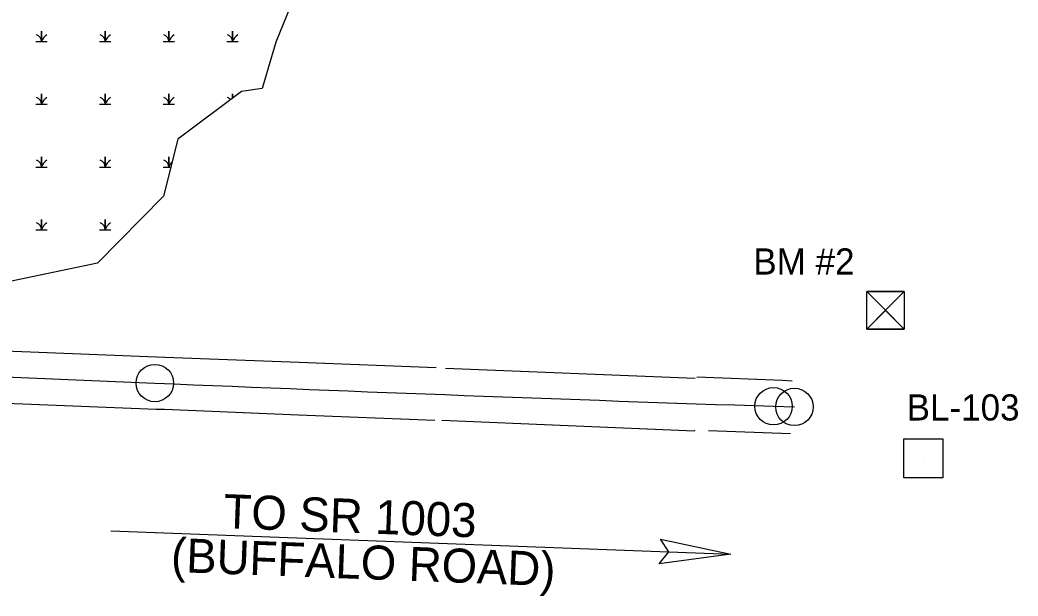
# Model space of a CAD drawing. Extents: x 2169223 to 2172151, y 723262 to 725175.
# Drawn here: x 2171308.7 to 2171689.8, y 723974.6 to 724194.7 of the extents above; entities that cross this region are included whole.
import ezdxf

# ---------------------------------------------------------------- set-up
doc = ezdxf.new("R2010")
doc.units = 0
for name, color, linetype in [('CTL Bench Mark CELL', 7, 'Continuous'), ('CTL Bench Mark Text', 7, 'Continuous'), ('CTL Supplemental Horizontal and Vertical CELL', 7, 'Continuous'), ('CTL Supplemental Horizontal and Vertical Text', 7, 'Continuous'), ('Default', 7, 'Continuous'), ('Exist Roads EOP', 7, 'Continuous'), ('Prop Horizontal Alignment', 7, 'Continuous'), ('Prop Horizontal Alignment Station Label', 7, 'Continuous')]:
    doc.layers.add(name, color=color, linetype=linetype)

# ---------------------------------------------------------------- blocks, each defined once
blk = doc.blocks.new('CTL BENCH MARK')
at = {"layer": 'CTL Bench Mark CELL'}
blk.add_line((0, 0), (0, 0), dxfattribs=at)
blk.add_lwpolyline([(-0.072, 0.07175), (0.07175, 0.07175), (0.07175, -0.072), (-0.072, -0.072)], close=True, dxfattribs=at)
for points in [[(0.07175, 0.07175), (-0.072, -0.072), (-0.000125, -0.000125), (0.07175, -0.072), (-0.072, 0.07175)], [(-0.000125, -0.000125), (0.07175, 0.07175), (-0.072, 0.07175), (-0.000125, -0.000125)], [(-0.000125, -0.000125), (-0.072, -0.072), (0.07175, -0.072), (-0.000125, -0.000125)]]:
    blk.add_lwpolyline(points, dxfattribs=at)
blk = doc.blocks.new('CTL SUPPLEMENTAL HORIZONTAL AND VERTICAL')
at = {"layer": 'CTL Supplemental Horizontal and Vertical CELL'}
blk.add_line((0, 0), (0, 0), dxfattribs=at)
blk.add_lwpolyline([(-0.0735, 0.074), (0.07475, 0.074), (0.07475, -0.0745), (-0.0735, -0.0745)], close=True, dxfattribs=at)

msp = doc.modelspace()

# ---------------------------------------------------------------- linework, layer by layer
at = {"layer": 'Default'}
msp.add_line((2171343.36, 723999.51), (2171580.07, 723990.65), dxfattribs=at)
for points in [[(2171646.71, 724409.08), (2171639.12, 724404.07), (2171615.95, 724359.66), (2171585.14, 724346.96), (2171572.27, 724330.12), (2171541.38, 724278.6), (2171494.05, 724272.59), (2171450.52, 724247.37), (2171445.92, 724243.67), (2171427.74, 724238.82), (2171406.38, 724186.3), (2171401.13, 724168.54), (2171393.3, 724167.45), (2171368.95, 724149.15), (2171363.45, 724127.38), (2171338.31, 724101.83), (2171299.81, 724093.74), (2171257.11, 724087.08), (2171085.47, 724098.48), (2171084.69, 724158.24), (2171059.94, 724158.08), (2171055.72, 724108.27), (2171040.51, 724083.75)], [(2171314.75, 724186.45), (2171316.9, 724186.45), (2171316.9, 724190.4), (2171316.9, 724186.45), (2171319.05, 724186.45)], [(2171339.06, 724186.45), (2171341.21, 724186.45), (2171341.21, 724190.4), (2171341.21, 724186.45), (2171343.36, 724186.45)], [(2171363.37, 724186.45), (2171365.53, 724186.45), (2171365.53, 724190.4), (2171365.53, 724186.45), (2171367.68, 724186.45)], [(2171387.69, 724186.45), (2171389.84, 724186.45), (2171389.84, 724190.4), (2171389.84, 724186.45), (2171391.99, 724186.45)], [(2171314.75, 724162.5), (2171316.9, 724162.5), (2171316.9, 724166.45), (2171316.9, 724162.5), (2171319.05, 724162.5)], [(2171339.06, 724162.5), (2171341.21, 724162.5), (2171341.21, 724166.45), (2171341.21, 724162.5), (2171343.36, 724162.5)], [(2171363.37, 724162.5), (2171365.53, 724162.5), (2171365.53, 724166.45), (2171365.53, 724162.5), (2171367.68, 724162.5)], [(2171389.84, 724164.85), (2171389.84, 724166.45), (2171389.84, 724164.85)], [(2171314.75, 724138.55), (2171316.9, 724138.55), (2171316.9, 724142.5), (2171316.9, 724138.55), (2171319.05, 724138.55)], [(2171339.06, 724138.55), (2171341.21, 724138.55), (2171341.21, 724142.5), (2171341.21, 724138.55), (2171343.36, 724138.55)], [(2171363.37, 724138.55), (2171365.53, 724138.55), (2171365.53, 724142.5), (2171365.53, 724138.55), (2171366.27, 724138.55)], [(2171314.75, 724114.6), (2171316.9, 724114.6), (2171316.9, 724118.55), (2171316.9, 724114.6), (2171319.05, 724114.6)], [(2171339.06, 724114.6), (2171341.21, 724114.6), (2171341.21, 724118.55), (2171341.21, 724114.6), (2171343.36, 724114.6)]]:
    msp.add_lwpolyline(points, dxfattribs=at)
msp.add_lwpolyline([(2171553.27, 723996.31), (2171580.07, 723990.65), (2171552.76, 723986.87), (2171556.39, 723991.54)], close=True, dxfattribs=at)
for centre, radius, start, end in [((2171313.83, 724186.23), 3.07, 4.1403, 67.535), ((2171321.46, 724184.94), 4.81, 122.1274, 161.6222), ((2171338.15, 724186.23), 3.07, 4.1403, 67.535), ((2171345.77, 724184.94), 4.81, 122.1274, 161.6222), ((2171362.46, 724186.23), 3.07, 4.1403, 67.535), ((2171370.09, 724184.94), 4.81, 122.1274, 161.6222), ((2171386.77, 724186.23), 3.07, 4.1403, 67.535), ((2171394.4, 724184.94), 4.81, 122.1274, 161.6222), ((2171313.83, 724162.28), 3.07, 4.1403, 67.535), ((2171321.46, 724160.99), 4.81, 122.1274, 161.6222), ((2171338.15, 724162.28), 3.07, 4.1403, 67.535), ((2171345.77, 724160.99), 4.81, 122.1274, 161.6222), ((2171362.46, 724162.28), 3.07, 4.1403, 67.535), ((2171370.09, 724160.99), 4.81, 122.1274, 161.6222), ((2171386.77, 724162.28), 3.07, 40.9383, 67.535), ((2171313.83, 724138.33), 3.07, 4.1403, 67.535), ((2171321.46, 724137.04), 4.81, 122.1274, 161.6222), ((2171338.15, 724138.33), 3.07, 4.1403, 67.535), ((2171345.77, 724137.04), 4.81, 122.1274, 161.6222), ((2171362.46, 724138.33), 3.07, 4.1403, 67.535), ((2171370.09, 724137.04), 4.81, 133.6686, 161.6222), ((2171313.83, 724114.38), 3.07, 4.1403, 67.535), ((2171321.46, 724113.09), 4.81, 122.1274, 161.6222), ((2171338.15, 724114.38), 3.07, 4.1403, 67.535), ((2171345.77, 724113.09), 4.81, 122.1274, 161.6222)]:
    msp.add_arc(centre, radius, start, end, dxfattribs=at)
at = {"layer": 'Exist Roads EOP'}
for p, q in [((2171471.18, 724061.72), (2171566.46, 724057.83)), ((2171469.78, 724041.77), (2171566.18, 724037.71)), ((2171571.58, 724037.9), (2171602.91, 724036.69))]:
    msp.add_line(p, q, dxfattribs=at)
for points in [[(2171363.96, 724065.89), (2171415.29, 724063.96), (2171467.56, 724061.94)], [(2171567.11, 724058.34), (2171599.87, 724057.09), (2171603.54, 724056.87)], [(2171363.8, 724045.97), (2171414.97, 724043.91), (2171467.12, 724041.87)]]:
    msp.add_lwpolyline(points, dxfattribs=at)
msp.add_ellipse((2171448.5, 724045.59), major_axis=(118.65, -4.51), ratio=0.241137, start_param=6.164089, end_param=6.175583, dxfattribs=at)
for points in [[(2171160.05, 724074.32), (2171211.12, 724072.58), (2171260.44, 724069.94), (2171312.64, 724067.9), (2171363.96, 724065.89)], [(2171159.83, 724055.04), (2171211.06, 724052.72), (2171260.56, 724050.29), (2171313.01, 724047.9), (2171363.8, 724045.97)]]:
    msp.add_spline(points, degree=3, dxfattribs=at)
at = {"layer": 'Prop Horizontal Alignment'}
for p, q in [((2170914.62, 724074.81), (2171360.17, 724056)), ((2171596.4, 724047.13), (2171604.38, 724046.87))]:
    msp.add_line(p, q, dxfattribs=at)
msp.add_arc((2172429.67, 749389.02), 25355.59, 267.582543, 268.116723, dxfattribs=at)
at = {"layer": 'Prop Horizontal Alignment Station Label'}
for centre in [(2171360.17, 724056), (2171596.4, 724047.13), (2171604.38, 724046.87)]:
    msp.add_circle(centre, 7.15, dxfattribs=at)

# ---------------------------------------------------------------- block references
at = {"layer": 'CTL Bench Mark CELL', "xscale": 100, "yscale": 100}
msp.add_blockref('CTL BENCH MARK', (2171639.17, 724083.82), dxfattribs=at)
at = {"layer": 'CTL Supplemental Horizontal and Vertical CELL', "xscale": 100, "yscale": 100}
msp.add_blockref('CTL SUPPLEMENTAL HORIZONTAL AND VERTICAL', (2171653.53, 724027.29), dxfattribs=at)

# ---------------------------------------------------------------- texts
at = {"layer": 'CTL Bench Mark Text'}
msp.add_text('BM #2', height=10, rotation=0, dxfattribs=at).set_placement((2171588.69, 724097.45))
at = {"layer": 'CTL Supplemental Horizontal and Vertical Text'}
msp.add_text('BL-103', height=10, rotation=0, dxfattribs=at).set_placement((2171647.23, 724041.69))
at = {"layer": 'Default'}
for s, p in [('TO SR 1003', (2171386.2, 724000.6)), ('(BUFFALO ROAD)', (2171366.2, 723983.85))]:
    msp.add_text(s, height=13, rotation=357.8574, dxfattribs=at).set_placement(p)

doc.saveas('drawing.dxf')
